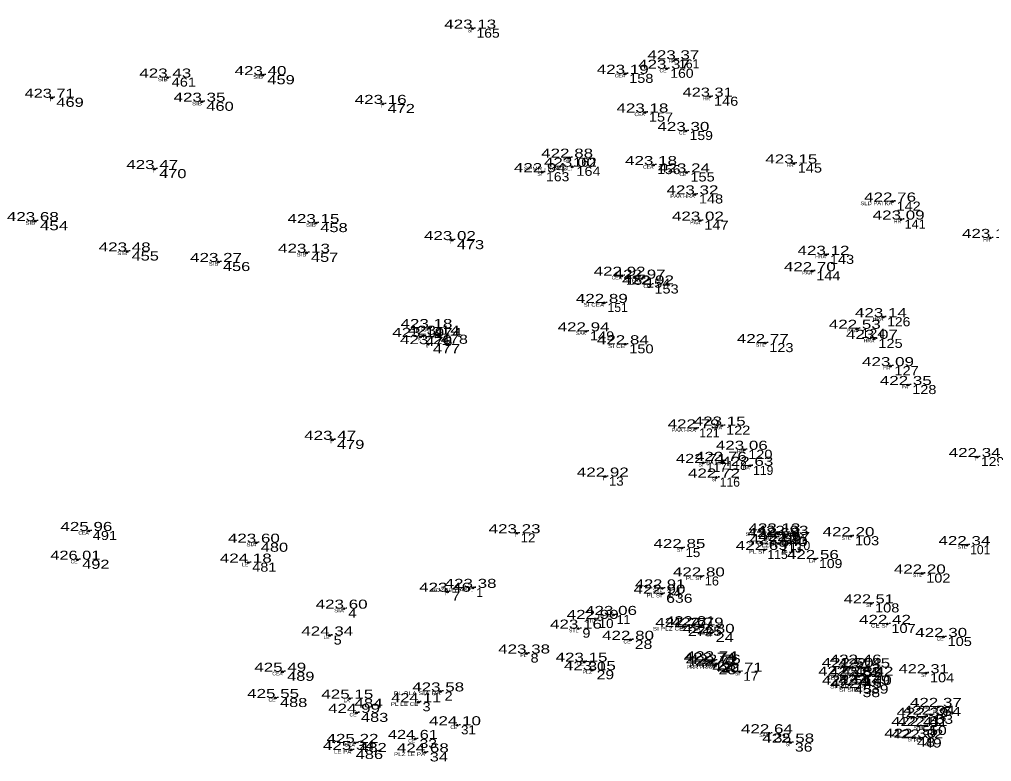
# Model space of a CAD drawing. Extents: x -639373 to -639056, y -1138651 to -1138359.
# Drawn here: x -639181.9 to -639101.4, y -1138650.6 to -1138589.2 of the extents above; entities that cross this region are included whole.
import ezdxf
from ezdxf.enums import TextEntityAlignment as Align

# ---------------------------------------------------------------- set-up
doc = ezdxf.new("R2010")
doc.units = 0
doc.header["$LTSCALE"] = 0.3
doc.header["$PDMODE"] = 32
doc.header["$PDSIZE"] = 0.15
for name, color, linetype in [('11', 7, 'Continuous'), ('12', 7, 'Continuous'), ('13', 7, 'Continuous'), ('14', 7, 'Continuous'), ('57', 7, 'Continuous')]:
    doc.layers.add(name, color=color, linetype=linetype)

msp = doc.modelspace()

# ---------------------------------------------------------------- linework, layer by layer
at = {"layer": '11'}
for p in [(-639144.39, -1138589.97), (-639127.58, -1138592.51), (-639128.35, -1138593.29), (-639169.62, -1138594.02), (-639161.74, -1138593.82), (-639131.77, -1138593.71), (-639179.2, -1138595.69), (-639124.75, -1138595.6), (-639166.79, -1138596.02), (-639151.8, -1138596.2), (-639130.14, -1138596.91), (-639126.75, -1138598.44), (-639136.37, -1138600.65), (-639170.7, -1138601.59), (-639136.14, -1138601.4), (-639129.43, -1138601.26), (-639117.82, -1138601.13), (-639138.63, -1138601.85), (-639126.7, -1138601.87), (-639126, -1138603.69), (-639109.65, -1138604.28), (-639180.58, -1138605.9), (-639157.36, -1138606.06), (-639125.55, -1138605.86), (-639108.94, -1138605.77), (-639146.07, -1138607.47), (-639101.55, -1138607.29), (-639172.98, -1138608.41), (-639158.14, -1138608.52), (-639115.16, -1138608.69), (-639165.42, -1138609.28), (-639132.03, -1138610.42), (-639116.29, -1138610.04), (-639130.37, -1138610.66), (-639129.68, -1138611.14), (-639133.5, -1138612.67), (-639110.41, -1138613.85), (-639148.01, -1138614.75), (-639135.01, -1138615.02), (-639112.57, -1138614.81), (-639148.69, -1138615.48), (-639148.05, -1138616.08), (-639147.41, -1138615.3), (-639120.18, -1138615.99), (-639111.15, -1138615.64), (-639131.76, -1138616.09), (-639109.82, -1138617.9), (-639108.35, -1138619.46), (-639125.91, -1138623.05), (-639123.75, -1138622.82), (-639155.98, -1138624), (-639121.92, -1138624.82), (-639102.65, -1138625.42), (-639125.3, -1138625.91), (-639123.65, -1138625.74), (-639121.46, -1138626.15), (-639133.42, -1138627.04), (-639124.22, -1138627.12), (-639176.15, -1138631.54), (-639140.72, -1138631.73), (-639119.3, -1138632.04), (-639119.22, -1138631.66), (-639118.55, -1138631.86), (-639113.09, -1138631.97), (-639162.29, -1138632.51), (-639127.08, -1138632.95), (-639119.12, -1138632.58), (-639118.41, -1138632.37), (-639103.5, -1138632.71), (-639120.27, -1138633.11), (-639177.07, -1138633.92), (-639162.96, -1138634.16), (-639116.04, -1138633.86), (-639125.47, -1138635.3), (-639107.19, -1138635.06), (-639146.47, -1138636.57), (-639144.36, -1138636.25), (-639128.73, -1138636.73), (-639128.69, -1138636.29), (-639111.42, -1138637.53), (-639155.03, -1138637.97), (-639132.74, -1138638.49), (-639134.26, -1138638.82), (-639126.19, -1138639.34), (-639110.07, -1138639.23), (-639156.22, -1138640.19), (-639135.64, -1138639.62), (-639126.93, -1138639.48), (-639125.57, -1138639.46), (-639124.66, -1138639.98), (-639131.33, -1138640.55), (-639105.42, -1138640.31), (-639139.93, -1138641.68), (-639135.18, -1138642.36), (-639124.58, -1138642.35), (-639124.41, -1138642.24), (-639124.15, -1138642.52), (-639112.5, -1138642.52), (-639160.11, -1138643.19), (-639134.49, -1138643.06), (-639124.39, -1138642.65), (-639122.29, -1138643.19), (-639113.16, -1138642.8), (-639111.79, -1138642.84), (-639106.88, -1138643.31), (-639113.52, -1138643.51), (-639112.54, -1138643.55), (-639111.52, -1138643.52), (-639147.04, -1138644.82), (-639113.22, -1138644.26), (-639112.48, -1138644.54), (-639111.79, -1138644.25), (-639160.7, -1138645.36), (-639154.56, -1138645.41), (-639148.87, -1138645.71), (-639154, -1138646.59), (-639105.86, -1138646.1), (-639106.97, -1138646.92), (-639106.44, -1138646.75), (-639145.65, -1138647.62), (-639107.49, -1138647.68), (-639106.97, -1138647.67), (-639149.14, -1138648.75), (-639119.84, -1138648.28), (-639118.08, -1138649.05), (-639107.99, -1138648.65), (-639107.39, -1138648.71), (-639154.43, -1138649.66), (-639154.13, -1138649.08), (-639148.31, -1138649.86)]:
    msp.add_point(p, dxfattribs=at)

# ---------------------------------------------------------------- texts
at = {"layer": '12'}
for s, width, p in [('422.88 ', 1.4, (-639136.37, -1138600.65)), ('423.00 ', 1.4, (-639136.14, -1138601.4)), ('423.32 ', 1.4, (-639126, -1138603.69)), ('422.76 ', 1.4, (-639109.649, -1138604.28)), ('423.02 ', 1.4, (-639125.55, -1138605.86)), ('423.12 ', 1.4, (-639115.16, -1138608.69)), ('422.70 ', 1.4, (-639116.29, -1138610.04)), ('423.14 ', 1.4, (-639110.41, -1138613.85)), ('422.53 ', 1.4, (-639112.57, -1138614.81)), ('423.07 ', 1.4, (-639111.15, -1138615.64)), ('423.09 ', 1.4, (-639109.82, -1138617.9)), ('422.35 ', 1.4, (-639108.35, -1138619.46)), ('422.79 ', 1.4, (-639125.91, -1138623.05)), ('423.15 ', 1.4, (-639123.75, -1138622.82)), ('423.06 ', 1.4, (-639121.919, -1138624.82)), ('422.34 ', 1.4, (-639102.65, -1138625.42)), ('422.76 ', 1.4, (-639123.649, -1138625.74)), ('422.63 ', 1.4, (-639121.46, -1138626.15)), ('425.96 ', 1.4, (-639176.149, -1138631.54)), ('423.13 ', 1.4, (-639119.22, -1138631.66)), ('422.20 ', 1.4, (-639113.09, -1138631.97)), ('423.60 ', 1.4, (-639162.29, -1138632.51)), ('422.34 ', 1.4, (-639103.5, -1138632.71)), ('426.01 ', 1.35, (-639177.069, -1138633.92)), ('424.18 ', 1.4, (-639162.96, -1138634.16)), ('422.56 ', 1.4, (-639116.039, -1138633.86)), ('422.20 ', 1.4, (-639107.19, -1138635.06)), ('422.90 ', 1.4, (-639128.73, -1138636.73)), ('422.51 ', 1.35, (-639111.419, -1138637.53)), ('423.60 ', 1.4, (-639155.03, -1138637.97)), ('423.06 ', 1.4, (-639132.739, -1138638.49)), ('422.42 ', 1.4, (-639110.07, -1138639.23)), ('422.77 ', 1.4, (-639126.93, -1138639.48)), ('422.81 ', 1.35, (-639126.189, -1138639.34)), ('422.79 ', 1.4, (-639125.57, -1138639.46)), ('422.80 ', 1.4, (-639124.66, -1138639.98)), ('424.34 ', 1.4, (-639156.22, -1138640.19)), ('422.80 ', 1.4, (-639131.33, -1138640.55)), ('422.30 ', 1.4, (-639105.42, -1138640.31)), ('423.38 ', 1.4, (-639139.93, -1138641.68)), ('423.15 ', 1.4, (-639135.18, -1138642.36)), ('422.74 ', 1.4, (-639124.58, -1138642.35)), ('422.74 ', 1.4, (-639124.41, -1138642.24)), ('425.49 ', 1.4, (-639160.11, -1138643.19)), ('423.15 ', 1.4, (-639134.49, -1138643.06)), ('422.72 ', 1.4, (-639124.39, -1138642.65)), ('422.76 ', 1.4, (-639124.149, -1138642.52)), ('422.71 ', 1.35, (-639122.289, -1138643.19)), ('422.50 ', 1.4, (-639113.16, -1138642.8)), ('422.46 ', 1.4, (-639112.499, -1138642.52)), ('422.45 ', 1.4, (-639111.79, -1138642.84)), ('422.31 ', 1.35, (-639106.879, -1138643.31)), ('422.51 ', 1.35, (-639113.519, -1138643.51)), ('422.53 ', 1.4, (-639112.54, -1138643.55)), ('422.42 ', 1.4, (-639111.52, -1138643.52)), ('423.58 ', 1.4, (-639147.04, -1138644.82)), ('422.51 ', 1.35, (-639113.219, -1138644.26)), ('422.45 ', 1.4, (-639112.48, -1138644.54)), ('422.49 ', 1.4, (-639111.79, -1138644.25)), ('425.55 ', 1.4, (-639160.7, -1138645.36)), ('425.15 ', 1.4, (-639154.56, -1138645.41)), ('424.11 ', 1.35, (-639148.869, -1138645.71)), ('422.37 ', 1.4, (-639105.86, -1138646.1)), ('424.99 ', 1.4, (-639154, -1138646.59)), ('422.39 ', 1.4, (-639106.97, -1138646.92)), ('422.34 ', 1.4, (-639106.44, -1138646.75)), ('424.10 ', 1.4, (-639145.65, -1138647.62)), ('422.41 ', 1.35, (-639107.489, -1138647.68)), ('422.41 ', 1.35, (-639106.969, -1138647.67)), ('424.61 ', 1.35, (-639149.139, -1138648.75)), ('422.64 ', 1.4, (-639119.84, -1138648.28)), ('422.30 ', 1.4, (-639107.99, -1138648.65)), ('422.32 ', 1.4, (-639107.39, -1138648.71)), ('425.34 ', 1.4, (-639154.43, -1138649.66)), ('425.22 ', 1.4, (-639154.13, -1138649.08)), ('422.58 ', 1.4, (-639118.08, -1138649.05)), ('424.68 ', 1.4, (-639148.31, -1138649.86))]:
    msp.add_text(s, height=0.75, dxfattribs=dict(at, width=width)).set_placement(p, align=Align.CENTER)
at = {"layer": '13'}
for s, width, p in [(' 165', 1.15, (-639144.39, -1138590.72)), (' 160', 1.15, (-639128.35, -1138594.04)), (' 461', 1.2, (-639169.62, -1138594.77)), (' 459', 1.35, (-639161.74, -1138594.57)), (' 158', 1.2, (-639131.77, -1138594.46)), (' 469', 1.35, (-639179.2, -1138596.44)), (' 146', 1.2, (-639124.75, -1138596.35)), (' 460', 1.35, (-639166.79, -1138596.77)), (' 472', 1.35, (-639151.8, -1138596.95)), (' 157', 1.2, (-639130.14, -1138597.66)), (' 159', 1.15, (-639126.75, -1138599.19)), (' 162', 1.15, (-639136.37, -1138601.4)), (' 164', 1.2, (-639136.14, -1138602.15)), (' 156', 1.15, (-639129.43, -1138602.01)), (' 145', 1.2, (-639117.82, -1138601.88)), (' 470', 1.35, (-639170.7, -1138602.34)), (' 163', 1.15, (-639138.63, -1138602.6)), (' 155', 1.2, (-639126.7, -1138602.62)), (' 148', 1.2, (-639126, -1138604.44)), (' 142', 1.2, (-639109.65, -1138605.03)), (' 454', 1.4, (-639180.58, -1138606.65)), (' 458', 1.35, (-639157.36, -1138606.81)), (' 147', 1.2, (-639125.55, -1138606.61)), (' 141', 1.05, (-639108.94, -1138606.52)), (' 473', 1.35, (-639146.07, -1138608.22)), (' 455', 1.35, (-639172.98, -1138609.16)), (' 457', 1.35, (-639158.14, -1138609.27)), (' 143', 1.2, (-639115.16, -1138609.44)), (' 456', 1.35, (-639165.42, -1138610.03)), (' 144', 1.2, (-639116.29, -1138610.79)), (' 152', 1.2, (-639132.03, -1138611.17)), (' 154', 1.2, (-639130.37, -1138611.41)), (' 153', 1.2, (-639129.68, -1138611.89)), (' 126', 1.15, (-639110.41, -1138614.6)), (' 474', 1.4, (-639148.01, -1138615.5)), (' 149', 1.2, (-639135.01, -1138615.77)), (' 124', 1.2, (-639112.57, -1138615.56)), (' 476', 1.35, (-639148.69, -1138616.23)), (' 478', 1.35, (-639147.41, -1138616.05)), (' 123', 1.2, (-639120.18, -1138616.74)), (' 125', 1.2, (-639111.15, -1138616.39)), (' 477', 1.35, (-639148.05, -1138616.83)), (' 150', 1.2, (-639131.76, -1138616.84)), (' 127', 1.2, (-639109.82, -1138618.65)), (' 128', 1.2, (-639108.35, -1138620.21)), (' 122', 1.2, (-639123.75, -1138623.57)), (' 479', 1.35, (-639155.98, -1138624.75)), (' 120', 1.2, (-639121.92, -1138625.57)), (' 129', 1.15, (-639102.65, -1138626.17)), (' 13', 1.1, (-639133.42, -1138627.79)), (' 491', 1.2, (-639176.15, -1138632.29)), (' 12', 1.1, (-639140.72, -1138632.48)), (' 640', 1.35, (-639119.3, -1138632.79)), (' 111', 0.9, (-639118.55, -1138632.61)), (' 103', 1.2, (-639113.09, -1138632.72)), (' 480', 1.35, (-639162.29, -1138633.26)), (' 15', 1.1, (-639127.08, -1138633.7)), (' 492', 1.35, (-639177.07, -1138634.67)), (' 481', 1.2, (-639162.96, -1138634.91)), (' 109', 1.15, (-639116.04, -1138634.61)), (' 16', 1.05, (-639125.47, -1138636.05)), (' 102', 1.2, (-639107.19, -1138635.81)), (' 7', 1.25, (-639146.47, -1138637.32)), (' 636', 1.3, (-639128.73, -1138637.48)), (' 14', 1.1, (-639128.69, -1138637.04)), (' 108', 1.2, (-639111.42, -1138638.28)), (' 4', 1.25, (-639155.03, -1138638.72)), (' 10', 1.1, (-639134.26, -1138639.57)), (' 26', 1.3, (-639126.19, -1138640.09)), (' 107', 1.2, (-639110.07, -1138639.98)), (' 9', 1.2, (-639135.64, -1138640.37)), (' 27', 1.3, (-639126.93, -1138640.23)), (' 25', 1.3, (-639125.57, -1138640.21)), (' 24', 1.35, (-639124.66, -1138640.73)), (' 5', 1.2, (-639156.22, -1138640.94)), (' 28', 1.3, (-639131.33, -1138641.3)), (' 105', 1.2, (-639105.42, -1138641.06)), (' 8', 1.2, (-639139.93, -1138642.43)), (' 30', 1.3, (-639135.18, -1138643.11)), (' 22', 1.3, (-639124.58, -1138643.1)), (' 21', 1.1, (-639124.41, -1138642.99)), (' 20', 1.3, (-639124.15, -1138643.27)), (' 42', 1.35, (-639112.5, -1138643.27)), (' 489', 1.35, (-639160.11, -1138643.94)), (' 29', 1.3, (-639134.49, -1138643.81)), (' 23', 1.3, (-639124.39, -1138643.4)), (' 17', 1.1, (-639122.29, -1138643.94)), (' 43', 1.35, (-639113.16, -1138643.55)), (' 41', 1.1, (-639111.79, -1138643.59)), (' 104', 1.2, (-639106.88, -1138644.06)), (' 44', 1.35, (-639113.52, -1138644.26)), (' 47', 1.35, (-639112.54, -1138644.3)), (' 40', 1.3, (-639111.52, -1138644.27)), (' 2', 1.2, (-639147.04, -1138645.57)), (' 45', 1.35, (-639113.22, -1138645.01)), (' 38', 1.3, (-639112.48, -1138645.29)), (' 39', 1.3, (-639111.79, -1138645)), (' 488', 1.35, (-639160.7, -1138646.11)), (' 484', 1.4, (-639154.56, -1138646.16)), (' 3', 1.2, (-639148.87, -1138646.46)), (' 54', 1.35, (-639105.86, -1138646.85)), (' 483', 1.35, (-639154, -1138647.34)), (' 52', 1.3, (-639106.97, -1138647.67)), (' 53', 1.3, (-639106.44, -1138647.5)), (' 31', 1.1, (-639145.65, -1138648.37)), (' 51', 1.1, (-639107.49, -1138648.43)), (' 50', 1.3, (-639106.97, -1138648.42)), (' 33', 1.3, (-639149.14, -1138649.5)), (' 35', 1.3, (-639119.84, -1138649.03)), (' 48', 1.35, (-639107.99, -1138649.4)), (' 49', 1.3, (-639107.39, -1138649.46)), (' 486', 1.35, (-639154.43, -1138650.41)), (' 482', 1.35, (-639154.13, -1138649.83)), (' 36', 1.3, (-639118.08, -1138649.8)), (' 34', 1.35, (-639148.31, -1138650.61))]:
    msp.add_text(s, height=0.75, dxfattribs=dict(at, width=width)).set_placement(p)
for s, p in [(' 161', (-639127.58, -1138593.26)), (' 151', (-639133.5, -1138613.42)), (' 121', (-639125.91, -1138623.8)), (' 117', (-639125.3, -1138626.66)), (' 118', (-639123.65, -1138626.49)), (' 119', (-639121.46, -1138626.9)), (' 116', (-639124.22, -1138627.87)), (' 112', (-639119.22, -1138632.41)), (' 113', (-639119.12, -1138633.33)), (' 110', (-639118.41, -1138633.12)), (' 101', (-639103.5, -1138633.46)), (' 115', (-639120.27, -1138633.86)), (' 1', (-639144.36, -1138637)), (' 11', (-639132.74, -1138639.24))]:
    msp.add_text(s, height=0.75, dxfattribs=at).set_placement(p)
at = {"layer": '14'}
for s, width, p in [('423.13 ', 1.4, (-639144.39, -1138589.97)), ('423.37 ', 1.4, (-639127.58, -1138592.51)), ('423.37 ', 1.4, (-639128.35, -1138593.29)), ('423.43 ', 1.4, (-639169.62, -1138594.02)), ('423.40 ', 1.4, (-639161.74, -1138593.82)), ('423.19 ', 1.4, (-639131.77, -1138593.71)), ('423.71 ', 1.35, (-639179.199, -1138595.69)), ('423.31 ', 1.35, (-639124.749, -1138595.6)), ('423.35 ', 1.4, (-639166.79, -1138596.02)), ('423.16 ', 1.4, (-639151.799, -1138596.2)), ('423.18 ', 1.4, (-639130.14, -1138596.91)), ('423.30 ', 1.4, (-639126.75, -1138598.44)), ('423.18 ', 1.4, (-639129.43, -1138601.26)), ('423.15 ', 1.4, (-639117.82, -1138601.13)), ('423.47 ', 1.4, (-639170.7, -1138601.59)), ('422.94 ', 1.4, (-639138.63, -1138601.85)), ('423.24 ', 1.4, (-639126.7, -1138601.87)), ('423.68 ', 1.4, (-639180.58, -1138605.9)), ('423.15 ', 1.4, (-639157.36, -1138606.06)), ('423.09 ', 1.4, (-639108.94, -1138605.77)), ('423.02 ', 1.4, (-639146.07, -1138607.47)), ('423.12 ', 1.4, (-639101.55, -1138607.29)), ('423.48 ', 1.4, (-639172.98, -1138608.41)), ('423.13 ', 1.4, (-639158.14, -1138608.52)), ('423.27 ', 1.4, (-639165.42, -1138609.28)), ('422.92 ', 1.4, (-639132.03, -1138610.42)), ('422.97 ', 1.4, (-639130.37, -1138610.66)), ('422.92 ', 1.4, (-639129.68, -1138611.14)), ('422.89 ', 1.4, (-639133.5, -1138612.67)), ('423.18 ', 1.4, (-639148.01, -1138614.75)), ('422.94 ', 1.4, (-639135.01, -1138615.02)), ('423.19 ', 1.4, (-639148.69, -1138615.48)), ('423.14 ', 1.4, (-639147.41, -1138615.3)), ('423.20 ', 1.4, (-639148.05, -1138616.08)), ('422.84 ', 1.4, (-639131.76, -1138616.09)), ('422.77 ', 1.4, (-639120.18, -1138615.99)), ('423.47 ', 1.4, (-639155.98, -1138624)), ('422.71 ', 1.35, (-639125.299, -1138625.91)), ('422.92 ', 1.4, (-639133.42, -1138627.04)), ('422.72 ', 1.4, (-639124.22, -1138627.12)), ('423.23 ', 1.4, (-639140.72, -1138631.73)), ('422.69 ', 1.4, (-639119.3, -1138632.04)), ('422.93 ', 1.4, (-639118.55, -1138631.86)), ('422.69 ', 1.4, (-639119.12, -1138632.58)), ('422.57 ', 1.4, (-639118.41, -1138632.37)), ('422.85 ', 1.4, (-639127.08, -1138632.95)), ('422.69 ', 1.4, (-639120.27, -1138633.11)), ('422.80 ', 1.4, (-639125.47, -1138635.3)), ('423.46 ', 1.4, (-639146.469, -1138636.57)), ('423.38 ', 1.4, (-639144.36, -1138636.25)), ('422.91 ', 1.35, (-639128.689, -1138636.29)), ('422.90 ', 1.4, (-639134.26, -1138638.82)), ('423.16 ', 1.4, (-639135.639, -1138639.62))]:
    msp.add_text(s, height=0.75, dxfattribs=dict(at, width=width)).set_placement(p, align=Align.CENTER)
at = {"layer": '57'}
for s, width, p in [('SI', 1.05, (-639144.39, -1138590.27)), ('HR', 0.85, (-639127.579, -1138592.81)), ('CE', 0.9, (-639128.35, -1138593.59)), ('SIB', 1.25, (-639169.619, -1138594.32)), ('SIB', 1.25, (-639161.739, -1138594.12)), ('T', 0.85, (-639179.2, -1138595.99)), ('HR', 0.85, (-639124.749, -1138595.9)), ('SIB', 1.25, (-639166.789, -1138596.32)), ('T', 0.85, (-639151.8, -1138596.5)), ('CE', 0.9, (-639126.75, -1138598.74)), ('SPMR - KOV.SL.', 1.3, (-639136.139, -1138601.7)), ('HR', 0.85, (-639117.819, -1138601.43)), ('T', 0.85, (-639170.7, -1138601.89)), ('SI', 1.05, (-639138.63, -1138602.15)), ('CE', 0.9, (-639126.7, -1138602.17)), ('PAA HRA', 1.15, (-639126, -1138603.99)), ('SLD PATKA', 1.2, (-639109.65, -1138604.58)), ('SIB', 1.25, (-639180.579, -1138606.2)), ('SIB', 1.25, (-639157.359, -1138606.36)), ('HR', 0.85, (-639108.939, -1138606.07)), ('T', 0.85, (-639146.07, -1138607.77)), ('HR', 0.85, (-639101.549, -1138607.59)), ('SIB', 1.25, (-639172.979, -1138608.71)), ('SIB', 1.25, (-639158.139, -1138608.82)), ('HRA', 0.95, (-639115.16, -1138608.99)), ('SIB', 1.25, (-639165.419, -1138609.58)), ('CE', 0.9, (-639129.68, -1138611.44)), ('SI CEA', 1.3, (-639133.5, -1138612.97)), ('HRA', 0.95, (-639110.41, -1138614.15)), ('K KA', 1.2, (-639148.01, -1138615.05)), ('K', 0.65, (-639148.689, -1138615.78)), ('K KA', 1.2, (-639147.41, -1138615.6)), ('STL', 1.05, (-639120.179, -1138616.29)), ('HRA', 0.95, (-639111.15, -1138615.94)), ('K', 0.65, (-639148.049, -1138616.38)), ('SI CE', 1.35, (-639131.76, -1138616.39)), ('HR', 0.85, (-639109.819, -1138618.2)), ('PA', 0.95, (-639108.35, -1138619.76)), ('PAA HRA', 1.15, (-639125.91, -1138623.35)), ('HRA', 0.95, (-639123.75, -1138623.12)), ('T', 0.85, (-639155.98, -1138624.3)), ('HR', 0.85, (-639121.919, -1138625.12)), ('T', 0.85, (-639102.65, -1138625.72)), ('SI', 1.05, (-639125.3, -1138626.21)), ('PA HR', 1.15, (-639123.649, -1138626.04)), ('PA', 0.95, (-639121.46, -1138626.45)), ('T', 0.85, (-639133.42, -1138627.34)), ('SI', 1.05, (-639124.22, -1138627.42)), ('T', 0.85, (-639140.72, -1138632.03)), ('STL - KER', 1.35, (-639119.219, -1138631.96)), ('PLZ', 1.1, (-639119.299, -1138632.34)), ('PLZA', 1.1, (-639118.55, -1138632.16)), ('STL', 1.05, (-639113.089, -1138632.27)), ('SIA', 1.25, (-639162.29, -1138632.81)), ('SI PLZ PLZA', 1.35, (-639118.41, -1138632.67)), ('PLZ PL', 1.25, (-639119.119, -1138632.88)), ('STL', 1.05, (-639103.499, -1138633.01)), ('SI', 1.05, (-639127.08, -1138633.25)), ('PL SI', 1.3, (-639120.27, -1138633.41)), ('CE', 0.9, (-639177.07, -1138634.22)), ('PL SI', 1.3, (-639125.47, -1138635.6)), ('STL', 1.05, (-639107.189, -1138635.36)), ('ROZBITY ASF.', 1.25, (-639144.359, -1138636.55)), ('T', 0.85, (-639146.47, -1138636.87)), ('PL SI', 1.3, (-639128.73, -1138637.03)), ('STL', 1.05, (-639128.689, -1138636.59)), ('SI', 1.05, (-639111.42, -1138637.83)), ('SIA', 1.25, (-639155.03, -1138638.27)), ('PL SI', 1.3, (-639132.74, -1138638.79)), ('STL', 1.05, (-639134.259, -1138639.12)), ('SI', 1.05, (-639126.19, -1138639.64)), ('CE SI', 1.3, (-639110.07, -1138639.53)), ('STL', 1.05, (-639135.639, -1138639.92)), ('SI PLZ CE', 1.35, (-639126.93, -1138639.78)), ('SI', 1.05, (-639125.57, -1138639.76)), ('SI', 1.05, (-639124.66, -1138640.28)), ('CE', 0.9, (-639131.33, -1138640.85)), ('CE', 0.9, (-639105.42, -1138640.61)), ('CE', 0.9, (-639135.18, -1138642.66)), ('PRR PRRA', 1.1, (-639124.15, -1138642.82)), ('PRR', 0.95, (-639124.579, -1138642.65)), ('PRR', 0.95, (-639124.409, -1138642.54)), ('SI', 1.05, (-639112.5, -1138642.82)), ('PLZ', 1.1, (-639134.489, -1138643.36)), ('PRR PRRA', 1.1, (-639124.39, -1138642.95)), ('SI', 1.05, (-639122.29, -1138643.49)), ('SI', 1.05, (-639113.16, -1138643.1)), ('SI', 1.05, (-639111.79, -1138643.14)), ('SI', 1.05, (-639106.88, -1138643.61)), ('SLB NN 2X', 1.25, (-639112.54, -1138643.85)), ('SI', 1.05, (-639113.52, -1138643.81)), ('SI', 1.05, (-639111.52, -1138643.82)), ('PL PLA SIA PA', 1.4, (-639147.04, -1138645.12)), ('SI SIB', 1.4, (-639113.219, -1138644.56)), ('SI SIB', 1.4, (-639112.479, -1138644.84)), ('SI', 1.05, (-639111.79, -1138644.55)), ('CE', 0.9, (-639160.7, -1138645.66)), ('PL LE CE', 1.3, (-639148.87, -1138646.01)), ('PL SI', 1.3, (-639105.86, -1138646.4)), ('CE', 0.9, (-639154, -1138646.89)), ('SI', 1.05, (-639106.97, -1138647.22)), ('CE', 0.9, (-639145.65, -1138647.92)), ('SI', 1.05, (-639107.49, -1138647.98)), ('CE', 0.9, (-639149.14, -1138649.05)), ('SI', 1.05, (-639107.99, -1138648.95)), ('LE PA', 1.25, (-639154.43, -1138649.96)), ('SI', 1.05, (-639118.08, -1138649.35)), ('PLZ LE PA', 1.3, (-639148.31, -1138650.16))]:
    msp.add_text(s, height=0.3, dxfattribs=dict(at, width=width)).set_placement(p, align=Align.RIGHT)
for s, p in [('CEA', (-639131.77, -1138594.01)), ('CEA', (-639130.14, -1138597.21)), ('LA', (-639136.37, -1138600.95)), ('CEA', (-639129.43, -1138601.56)), ('PAA', (-639125.55, -1138606.16)), ('PAA', (-639116.29, -1138610.34)), ('CEA', (-639132.03, -1138610.72)), ('STERK', (-639130.369, -1138610.96)), ('SAK', (-639135.009, -1138615.32)), ('PAA', (-639112.57, -1138615.11)), ('CEA', (-639176.15, -1138631.84)), ('LE', (-639162.96, -1138634.46)), ('LA', (-639116.04, -1138634.16)), ('LE', (-639156.22, -1138640.49)), ('PL', (-639139.929, -1138641.98)), ('CEA', (-639160.11, -1138643.49)), ('LA', (-639154.56, -1138645.71)), ('PL', (-639106.439, -1138647.05)), ('PL', (-639106.969, -1138647.97)), ('SAV', (-639119.84, -1138648.58)), ('PL', (-639107.389, -1138649.01)), ('CEA', (-639154.13, -1138649.38))]:
    msp.add_text(s, height=0.3, dxfattribs=at).set_placement(p, align=Align.RIGHT)

doc.saveas('drawing.dxf')
